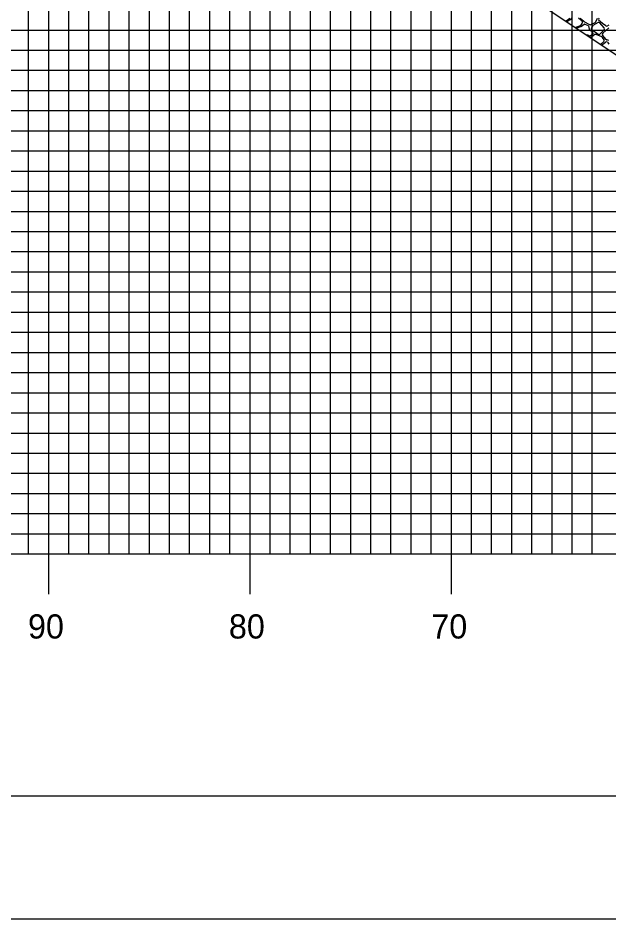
# Model space of a CAD drawing. Extents: x 1770055 to 1770398, y 442591 to 442811.
# Drawn here: x 1770129 to 1770158.36, y 442590.55 to 442635.26 of the extents above; entities that cross this region are included whole.
import ezdxf

# ---------------------------------------------------------------- set-up
doc = ezdxf.new("R2010")
doc.units = 0
for name, color, linetype in [('ANNOTATION', 7, 'Continuous'), ('BORDER', 7, 'Continuous'), ('GRUBBING IN FILL', 7, 'Continuous'), ('H_V ANNOTATION', 7, 'Continuous'), ('MAJOR', 7, 'Continuous'), ('MINOR', 7, 'Continuous'), ('PLOT BOUNDARY', 7, 'Continuous')]:
    doc.layers.add(name, color=color, linetype=linetype)

msp = doc.modelspace()

# ---------------------------------------------------------------- linework, layer by layer
at = {"layer": 'ANNOTATION'}
msp.add_lwpolyline([(1770184.69, 442616.106), (1770132.715, 442650.756), (1770131.718, 442651.337), (1770130.867, 442651.689), (1770130.079, 442651.882), (1770129.303, 442651.941)], dxfattribs=at)
at = {"layer": 'BORDER'}
msp.add_lwpolyline([(1770070.928, 442596.665), (1770390.928, 442596.665), (1770390.928, 442806.665), (1770070.928, 442806.665)], close=True, dxfattribs=at)
at = {"layer": 'GRUBBING IN FILL'}
for p, q in [((1770156.233, 442635.118), (1770156.41, 442635.26)), ((1770156.416, 442635.164), (1770156.324, 442635.118)), ((1770156.491, 442635.26), (1770156.442, 442635.187)), ((1770157.024, 442635.102), (1770156.843, 442635.26)), ((1770156.92, 442635.26), (1770157.101, 442635.098)), ((1770156.972, 442634.919), (1770157.035, 442635.012)), ((1770157.114, 442635.089), (1770157.393, 442634.936)), ((1770157.455, 442634.934), (1770157.664, 442635.033)), ((1770157.813, 442635.031), (1770157.559, 442634.891)), ((1770157.697, 442635.068), (1770157.78, 442635.26)), ((1770157.85, 442635.236), (1770157.868, 442635.26)), ((1770157.921, 442635.093), (1770157.861, 442635.141)), ((1770158.118, 442634.77), (1770157.897, 442635.017)), ((1770158.041, 442634.995), (1770157.921, 442635.092)), ((1770158.209, 442634.87), (1770158.043, 442634.994)), ((1770156.671, 442634.795), (1770156.939, 442634.892)), ((1770156.746, 442634.736), (1770156.759, 442634.75)), ((1770156.829, 442634.795), (1770156.948, 442634.837)), ((1770156.994, 442634.861), (1770157.121, 442634.956)), ((1770157.155, 442634.96), (1770157.318, 442634.888)), ((1770157.337, 442634.865), (1770157.375, 442634.708)), ((1770157.388, 442634.689), (1770157.523, 442634.589)), ((1770157.531, 442634.862), (1770157.486, 442634.773)), ((1770157.506, 442634.688), (1770157.817, 442634.45)), ((1770157.537, 442634.567), (1770157.551, 442634.478)), ((1770157.908, 442634.458), (1770158.117, 442634.677)), ((1770158.047, 442634.502), (1770158.358, 442634.776)), ((1770158.358, 442634.91), (1770158.285, 442634.867)), ((1770157.288, 442634.414), (1770157.232, 442634.411)), ((1770157.378, 442634.356), (1770157.311, 442634.407)), ((1770157.538, 442634.446), (1770157.42, 442634.355)), ((1770157.649, 442634.435), (1770157.483, 442634.312)), ((1770158.009, 442634.318), (1770157.716, 442634.443)), ((1770157.935, 442633.943), (1770158.102, 442634.089)), ((1770158.217, 442634.196), (1770158.04, 442634.407)), ((1770158.114, 442634.178), (1770158.04, 442634.293)), ((1770158.358, 442634.145), (1770158.251, 442634.174)), ((1770157.987, 442633.908), (1770158.188, 442634.067)), ((1770158.283, 442634.057), (1770158.358, 442633.966))]:
    msp.add_line(p, q, dxfattribs=at)
for centre, major_axis, start_param, end_param in [((1770156.19, 442635.171), (0, -0.0683), 0.06703, 0.674741), ((1770156.354, 442635.057), (0, 0.0683), 0.463648, 1.806421), ((1770156.385, 442635.225), (0, -0.0683), 0.463648, 0.97362), ((1770156.979, 442635.051), (0, -0.0683), 0.977446, 2.424153), ((1770157.146, 442635.149), (0, -0.0683), 5.554357, 5.782172), ((1770157.635, 442635.095), (0, -0.0683), 0.443382, 1.163165), ((1770157.846, 442634.971), (0, 0.0683), 5.44252, 6.785098), ((1770157.903, 442635.194), (0, -0.0683), 4.048343, 5.608444), ((1770157.878, 442635.039), (0, 0.0683), 5.600869, 5.608444), ((1770158.084, 442635.048), (0, -0.0683), 5.600869, 5.645637), ((1770156.648, 442634.86), (0, -0.0683), 0.18802, 0.347767), ((1770156.884, 442634.634), (0, 0.171), 0.333945, 0.825917), ((1770156.916, 442634.957), (0, -0.0683), 0.347767, 0.977446), ((1770156.892, 442634.998), (0, -0.171), 0.333945, 0.641659), ((1770157.141, 442634.929), (0, 0.0342), 5.866747, 6.924845), ((1770157.304, 442634.857), (0, 0.0342), 4.95256, 5.866747), ((1770157.408, 442634.716), (0, -0.0342), 4.95256, 5.649393), ((1770157.426, 442634.996), (0, -0.0683), 5.782172, 6.726567), ((1770157.547, 442634.743), (0, 0.0683), 1.108164, 2.48948), ((1770157.503, 442634.562), (0, 0.0342), 4.865038, 5.649393), ((1770157.592, 442634.832), (0, 0.0683), 0.501913, 1.108164), ((1770158.067, 442634.724), (0, -0.0683), 0.810393, 2.300927), ((1770158.25, 442634.925), (0, -0.0683), 5.645637, 6.81814), ((1770157.29, 442634.38), (0, 0.0342), 5.62749, 6.335377), ((1770157.399, 442634.383), (0, -0.0342), 5.62749, 6.938291), ((1770157.523, 442634.257), (0, 0.0683), 0.638914, 1.487471), ((1770157.517, 442634.473), (0, 0.0342), 3.796699, 4.865038), ((1770157.689, 442634.38), (0, 0.0683), 5.881372, 6.922099), ((1770157.859, 442634.505), (0, -0.0683), 5.631073, 7.093578), ((1770157.982, 442634.255), (0, 0.0683), 5.287694, 5.881372), ((1770158.092, 442634.451), (0, -0.0683), 3.861663, 5.40978), ((1770158.057, 442634.14), (0, -0.0683), 0.719883, 2.146101), ((1770158.23, 442634.014), (0, 0.0683), 5.401291, 6.952921), ((1770158.269, 442634.24), (0, -0.0683), 5.40978, 6.025862)]:
    msp.add_ellipse(centre, major_axis=major_axis, ratio=0.99895, start_param=start_param, end_param=end_param, dxfattribs=at)
at = {"layer": 'MAJOR'}
for p, q in [((1770130.528, 442608.665), (1770130.528, 442663.665)), ((1770140.528, 442608.665), (1770140.528, 442663.665)), ((1770150.528, 442608.665), (1770150.528, 442663.665)), ((1770080.528, 442633.665), (1770360.528, 442633.665)), ((1770080.528, 442628.665), (1770360.528, 442628.665)), ((1770080.528, 442623.665), (1770360.528, 442623.665)), ((1770080.528, 442618.665), (1770360.528, 442618.665)), ((1770080.528, 442613.665), (1770360.528, 442613.665)), ((1770080.528, 442608.665), (1770360.528, 442608.665)), ((1770080.528, 442608.665), (1770360.528, 442608.665)), ((1770130.528, 442606.661), (1770130.528, 442608.665)), ((1770140.528, 442606.661), (1770140.528, 442608.665)), ((1770150.528, 442606.661), (1770150.528, 442608.665))]:
    msp.add_line(p, q, dxfattribs=at)
at = {"layer": 'MINOR'}
for p, q in [((1770129.528, 442608.665), (1770129.528, 442663.665)), ((1770131.528, 442608.665), (1770131.528, 442663.665)), ((1770132.528, 442608.665), (1770132.528, 442663.665)), ((1770133.528, 442608.665), (1770133.528, 442663.665)), ((1770134.528, 442608.665), (1770134.528, 442663.665)), ((1770135.528, 442608.665), (1770135.528, 442663.665)), ((1770136.528, 442608.665), (1770136.528, 442663.665)), ((1770137.528, 442608.665), (1770137.528, 442663.665)), ((1770138.528, 442608.665), (1770138.528, 442663.665)), ((1770139.528, 442608.665), (1770139.528, 442663.665)), ((1770141.528, 442608.665), (1770141.528, 442663.665)), ((1770142.528, 442608.665), (1770142.528, 442663.665)), ((1770143.528, 442608.665), (1770143.528, 442663.665)), ((1770144.528, 442608.665), (1770144.528, 442663.665)), ((1770145.528, 442608.665), (1770145.528, 442663.665)), ((1770146.528, 442608.665), (1770146.528, 442663.665)), ((1770147.528, 442608.665), (1770147.528, 442663.665)), ((1770148.528, 442608.665), (1770148.528, 442663.665)), ((1770149.528, 442608.665), (1770149.528, 442663.665)), ((1770151.528, 442608.665), (1770151.528, 442663.665)), ((1770152.528, 442608.665), (1770152.528, 442663.665)), ((1770153.528, 442608.665), (1770153.528, 442663.665)), ((1770154.528, 442608.665), (1770154.528, 442663.665)), ((1770155.528, 442608.665), (1770155.528, 442663.665)), ((1770156.528, 442608.665), (1770156.528, 442663.665)), ((1770157.528, 442608.665), (1770157.528, 442663.665)), ((1770080.528, 442634.665), (1770360.528, 442634.665)), ((1770080.528, 442632.665), (1770360.528, 442632.665)), ((1770080.528, 442631.665), (1770360.528, 442631.665)), ((1770080.528, 442630.665), (1770360.528, 442630.665)), ((1770080.528, 442629.665), (1770360.528, 442629.665)), ((1770080.528, 442627.665), (1770360.528, 442627.665)), ((1770080.528, 442626.665), (1770360.528, 442626.665)), ((1770080.528, 442625.665), (1770360.528, 442625.665)), ((1770080.528, 442624.665), (1770360.528, 442624.665)), ((1770080.528, 442622.665), (1770360.528, 442622.665)), ((1770080.528, 442621.665), (1770360.528, 442621.665)), ((1770080.528, 442620.665), (1770360.528, 442620.665)), ((1770080.528, 442619.665), (1770360.528, 442619.665)), ((1770080.528, 442617.665), (1770360.528, 442617.665)), ((1770080.528, 442616.665), (1770360.528, 442616.665)), ((1770080.528, 442615.665), (1770360.528, 442615.665)), ((1770080.528, 442614.665), (1770360.528, 442614.665)), ((1770080.528, 442612.665), (1770360.528, 442612.665)), ((1770080.528, 442611.665), (1770360.528, 442611.665)), ((1770080.528, 442610.665), (1770360.528, 442610.665)), ((1770080.528, 442609.665), (1770360.528, 442609.665))]:
    msp.add_line(p, q, dxfattribs=at)
at = {"layer": 'PLOT BOUNDARY'}
msp.add_lwpolyline([(1770054.741, 442590.547), (1770394.741, 442590.547), (1770394.741, 442810.547), (1770054.741, 442810.547)], close=True, dxfattribs=at)

# ---------------------------------------------------------------- texts
at = {"layer": 'H_V ANNOTATION'}
for s, p in [('90', (1770129.5, 442604.465)), ('80', (1770139.479, 442604.465)), ('70', (1770149.532, 442604.465))]:
    msp.add_text(s, height=1.2, dxfattribs=at).set_placement(p)

doc.saveas('drawing.dxf')
